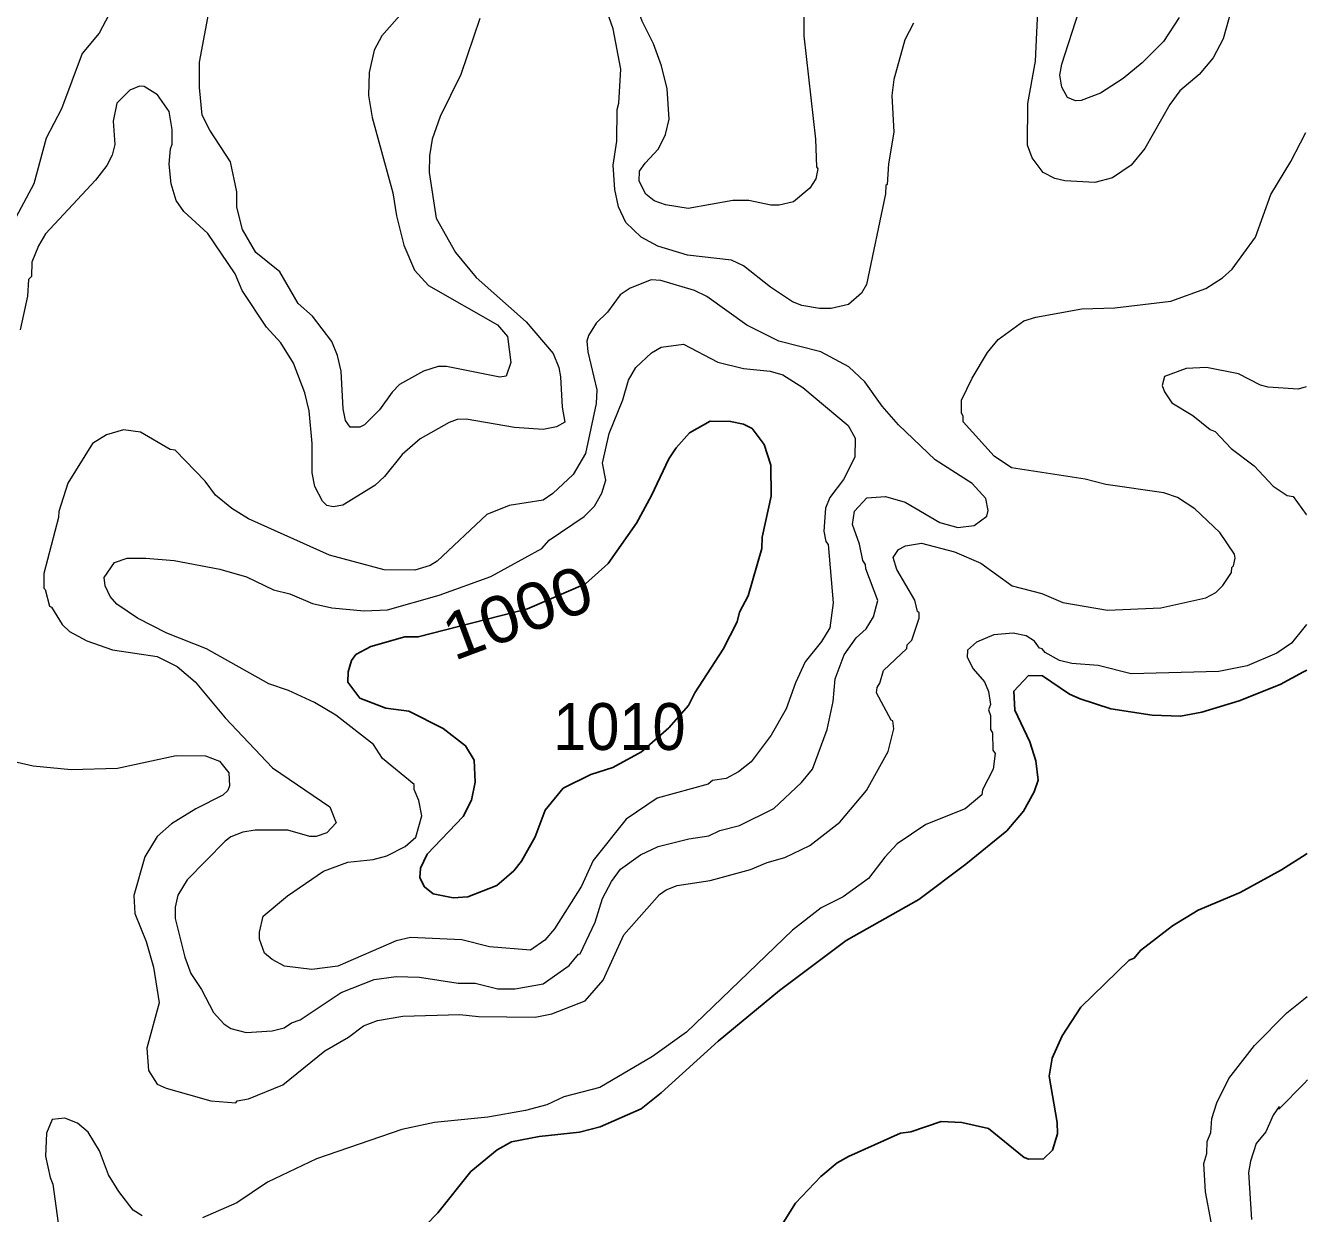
# Model space of a CAD drawing. Extents: x 447.8 to 473.9, y 7733.1 to 7760.8.
# Drawn here: x 471.729 to 473.918, y 7741.173 to 7743.202 of the extents above; entities that cross this region are included whole.
import ezdxf
from ezdxf.enums import TextEntityAlignment as Align

# ---------------------------------------------------------------- set-up
doc = ezdxf.new("R2010")
doc.units = 0
doc.header["$LTSCALE"] = 0.032
doc.layers.add('1', color=7, linetype='Continuous', lineweight=25)
doc.layers.add('2', color=7, linetype='Continuous', lineweight=13)
doc.layers.add('21', color=7, linetype='Continuous')
doc.layers.add('61', color=7, linetype='Continuous')

msp = doc.modelspace()

# ---------------------------------------------------------------- linework, layer by layer
at = {"layer": '1'}
msp.add_lwpolyline([(472.9864, 7742.3085), (472.9868, 7742.3279), (473.0027, 7742.3978), (473.0019, 7742.451), (472.9907, 7742.4862), (472.9699, 7742.5135), (472.9551, 7742.5208), (472.933, 7742.5255), (472.8981, 7742.5263), (472.8631, 7742.5061), (472.84, 7742.4806), (472.8277, 7742.4617), (472.798, 7742.399), (472.7721, 7742.3519), (472.724, 7742.2829), (472.6852, 7742.2483), (472.5862, 7742.2057), (472.3996, 7742.1574), (472.3767, 7742.1576), (472.3187, 7742.1414), (472.2928, 7742.1273), (472.2855, 7742.117), (472.2797, 7742.0978), (472.279, 7742.0802), (472.2998, 7742.0527), (472.3443, 7742.0358), (472.3835, 7742.0308), (472.4421, 7742.0012), (472.4803, 7741.9712), (472.4953, 7741.9471), (472.4969, 7741.9091), (472.4905, 7741.8787), (472.4764, 7741.8508), (472.4148, 7741.7865), (472.4031, 7741.7624), (472.4024, 7741.746), (472.4101, 7741.7303), (472.4248, 7741.7188), (472.4593, 7741.712), (472.4841, 7741.7136), (472.5335, 7741.7326), (472.5629, 7741.7579), (472.576, 7741.7744), (472.5994, 7741.8158), (472.6165, 7741.8616), (472.6471, 7741.8992), (472.6946, 7741.9223), (472.7319, 7741.9347), (472.7807, 7741.9613), (472.8275, 7742.0024), (472.8614, 7742.0404), (472.8723, 7742.0617), (472.9206, 7742.1365), (472.9442, 7742.1832), (472.9484, 7742.1996), (472.9633, 7742.2278)], close=True, dxfattribs=at)
for points in [[(472.3917, 7741.1313), (472.4327, 7741.1737), (472.4892, 7741.2441), (472.5344, 7741.2814), (472.5591, 7741.2952), (472.6061, 7741.3039), (472.6751, 7741.3117), (472.7104, 7741.3203), (472.7802, 7741.3514), (472.8147, 7741.3787), (472.912, 7741.4671), (473.0166, 7741.5535), (473.1307, 7741.639), (473.2548, 7741.7087), (473.3352, 7741.7694), (473.4049, 7741.8263), (473.4338, 7741.8601), (473.4516, 7741.8931), (473.4587, 7741.9125), (473.4548, 7741.946), (473.4443, 7741.9784), (473.4188, 7742.0321), (473.4173, 7742.0646), (473.4423, 7742.0918), (473.4662, 7742.0908), (473.5123, 7742.0599), (473.5302, 7742.0516), (473.5827, 7742.0349), (473.6532, 7742.0237), (473.7019, 7742.0221), (473.7381, 7742.029), (473.8022, 7742.0481), (473.8722, 7742.0764), (473.9118, 7742.0976), (473.9174, 7742.1006)], [(473.9179, 7741.7874), (473.9166, 7741.7866), (473.8744, 7741.7594), (473.8035, 7741.7208), (473.7319, 7741.6905), (473.6883, 7741.6642), (473.6334, 7741.6219), (473.6226, 7741.6088), (473.6141, 7741.6051), (473.5316, 7741.5249), (473.4997, 7741.476), (473.4826, 7741.4381), (473.4774, 7741.407), (473.4908, 7741.328), (473.4917, 7741.3088), (473.483, 7741.2809), (473.4679, 7741.2657), (473.4429, 7741.2655), (473.4349, 7741.2679), (473.3739, 7741.3175), (473.3282, 7741.3278), (473.2931, 7741.3295), (473.2412, 7741.3121), (473.2233, 7741.3095), (473.1347, 7741.2701), (473.1152, 7741.259), (473.0875, 7741.2356), (473.0442, 7741.19), (472.9609, 7741.0576)]]:
    msp.add_lwpolyline(points, dxfattribs=at)
at = {"layer": '2'}
for points in [[(472.0434, 7743.023), (472.0305, 7743.049), (472.0258, 7743.0961), (472.0257, 7743.1391), (472.04, 7743.215), (472.0416, 7743.2798)], [(471.8817, 7743.2407), (471.8541, 7743.1888), (471.8256, 7743.1544), (471.7898, 7743.0599), (471.7638, 7743.0096), (471.7425, 7742.9316), (471.7035, 7742.8578), (471.6892, 7742.84), (471.679, 7742.8333), (471.657, 7742.8366), (471.6426, 7742.8579), (471.6352, 7742.9095), (471.632, 7742.974), (471.6265, 7742.999), (471.617, 7743.0242), (471.6129, 7743.0499), (471.6121, 7743.14), (471.6292, 7743.1973), (471.6427, 7743.22)], [(473.7927, 7743.2439), (473.7748, 7743.1791), (473.7578, 7743.1469), (473.7336, 7743.1185), (473.7008, 7743.0904), (473.6838, 7743.0668), (473.641, 7742.9919), (473.6175, 7742.9633), (473.5858, 7742.9417), (473.5556, 7742.9336), (473.5041, 7742.9364), (473.4873, 7742.9405), (473.4672, 7742.9511), (473.4482, 7742.9759), (473.4405, 7742.9973), (473.4408, 7743.0687), (473.4541, 7743.141), (473.4589, 7743.2516)], [(472.3849, 7743.2384), (472.3371, 7743.1846), (472.324, 7743.1599), (472.3159, 7743.1218), (472.3143, 7743.0823), (472.3205, 7743.0448), (472.3559, 7742.9163), (472.3624, 7742.8771), (472.375, 7742.8268), (472.3929, 7742.7843), (472.4168, 7742.7577), (472.5351, 7742.6906), (472.5519, 7742.6709), (472.5578, 7742.6264), (472.5499, 7742.6029), (472.5389, 7742.6011), (472.4479, 7742.6193), (472.4337, 7742.6192), (472.4085, 7742.6112), (472.3677, 7742.5886), (472.3549, 7742.5757), (472.3332, 7742.5454), (472.3075, 7742.5199), (472.2995, 7742.5159), (472.2833, 7742.516), (472.2755, 7742.5273), (472.271, 7742.5469), (472.2677, 7742.6117), (472.2618, 7742.6381), (472.252, 7742.662), (472.2186, 7742.7054), (472.1946, 7742.727), (472.163, 7742.781), (472.122, 7742.8142), (472.0994, 7742.8535), (472.0898, 7742.8915), (472.0897, 7742.9179), (472.0785, 7742.9689), (472.0434, 7743.023)], [(473.2455, 7743.2059), (473.231, 7743.1776), (473.212, 7743.1099), (473.2087, 7743.0822), (473.2119, 7743.0198), (473.2027, 7742.9659), (473.2007, 7742.9306), (473.1982, 7742.9286), (473.1975, 7742.9147), (473.1652, 7742.7594), (473.1568, 7742.7445), (473.1343, 7742.7256), (473.105, 7742.7188), (473.085, 7742.7188), (473.0548, 7742.7239), (473.0391, 7742.7298), (473.0011, 7742.7549), (472.9549, 7742.7914), (472.9349, 7742.8012), (472.8593, 7742.8098), (472.809, 7742.8248), (472.7806, 7742.8404), (472.754, 7742.8654), (472.7418, 7742.8924), (472.7351, 7742.922), (472.7326, 7742.9632), (472.739, 7743.0042), (472.7391, 7743.0583), (472.7422, 7743.0693), (472.7454, 7743.1275), (472.7327, 7743.1961), (472.7182, 7743.2368)], [(472.828, 7743.0418), (472.8248, 7743.0938), (472.815, 7743.133), (472.8015, 7743.1708), (472.7822, 7743.2096), (472.7726, 7743.2356)], [(473.058, 7743.2269), (473.0582, 7743.1842), (473.0782, 7743.0077), (473.0798, 7742.9604), (473.082, 7742.9573), (473.0787, 7742.9401), (473.0685, 7742.9239), (473.0407, 7742.9008), (473.016, 7742.8952), (473.0016, 7742.8951), (472.9642, 7742.9031), (472.9371, 7742.9031), (472.8609, 7742.8894), (472.8222, 7742.8959), (472.8024, 7742.9026), (472.7884, 7742.9138), (472.7767, 7742.9359), (472.7777, 7742.9529), (472.7869, 7742.9669), (472.8097, 7742.9915), (472.822, 7743.0157), (472.828, 7743.0418)], [(473.6992, 7743.2155), (473.6726, 7743.1745), (473.6365, 7743.1384), (473.6037, 7743.1113), (473.5652, 7743.0865), (473.5323, 7743.0738), (473.5223, 7743.0731), (473.5085, 7743.0789), (473.4991, 7743.0969), (473.4958, 7743.117), (473.4991, 7743.1362), (473.5278, 7743.2257)], [(472.5048, 7743.2139), (472.4722, 7743.1182), (472.4371, 7743.0463), (472.4234, 7743.008), (472.4185, 7742.9791), (472.4183, 7742.9507), (472.4304, 7742.8729), (472.4634, 7742.8144), (472.4986, 7742.7715), (472.5841, 7742.6956), (472.63, 7742.6417), (472.6396, 7742.6177), (472.6428, 7742.6017), (472.6453, 7742.5499), (472.65, 7742.5245), (472.6359, 7742.5165), (472.613, 7742.512), (472.5637, 7742.5152), (472.4816, 7742.5295), (472.466, 7742.5287), (472.4523, 7742.524), (472.4026, 7742.4961), (472.3723, 7742.4689), (472.342, 7742.4315), (472.3256, 7742.4164), (472.2709, 7742.3824), (472.2544, 7742.3797), (472.2433, 7742.3822), (472.236, 7742.3896), (472.2229, 7742.4142), (472.2181, 7742.4378), (472.218, 7742.4881), (472.2132, 7742.544), (472.2057, 7742.5745), (472.1862, 7742.6251), (472.1649, 7742.6597), (472.1402, 7742.6865), (472.0984, 7742.7495), (472.0865, 7742.778), (472.0398, 7742.8464), (471.999, 7742.8841), (471.9857, 7742.9028), (471.9776, 7742.9316), (471.9739, 7742.9651), (471.976, 7742.9912), (471.9791, 7742.9994), (471.9792, 7743.0241), (471.9737, 7743.0548), (471.9543, 7743.0834), (471.931, 7743.0978), (471.9231, 7743.0985), (471.9068, 7743.0913), (471.8848, 7743.0692), (471.8782, 7743.0388), (471.8812, 7742.9987), (471.8766, 7742.9803), (471.8675, 7742.9626), (471.8481, 7742.9378), (471.7627, 7742.8462), (471.7506, 7742.8258), (471.7395, 7742.7976), (471.7386, 7742.773), (471.7339, 7742.7681), (471.7322, 7742.7396), (471.7195, 7742.6821)], [(473.1944, 7742.0999), (473.2343, 7742.1376), (473.2349, 7742.144), (473.2426, 7742.1519), (473.2552, 7742.1898), (473.2552, 7742.1989), (473.2522, 7742.201), (473.2478, 7742.2203), (473.2172, 7742.2724), (473.2106, 7742.2932), (473.2199, 7742.3071), (473.2319, 7742.3132), (473.259, 7742.3179), (473.3156, 7742.3029), (473.3607, 7742.2836), (473.4141, 7742.2447), (473.4649, 7742.2314), (473.5007, 7742.2165), (473.5772, 7742.2034), (473.6679, 7742.2074), (473.7448, 7742.2244), (473.7623, 7742.2333), (473.7743, 7742.2453), (473.7891, 7742.2678), (473.7892, 7742.2759), (473.7922, 7742.2787), (473.7953, 7742.292), (473.7939, 7742.2987), (473.7688, 7742.3357), (473.726, 7742.3761), (473.6964, 7742.3956), (473.6734, 7742.4038), (473.5743, 7742.4178), (473.5387, 7742.427), (473.4133, 7742.4465), (473.3834, 7742.4663), (473.3307, 7742.5251), (473.3306, 7742.5348), (473.3275, 7742.5395), (473.3275, 7742.562), (473.3456, 7742.5996), (473.3718, 7742.6436), (473.3905, 7742.6655), (473.4339, 7742.6974), (473.4544, 7742.7036), (473.533, 7742.718), (473.5894, 7742.7196), (473.6855, 7742.7313), (473.7448, 7742.7527), (473.7733, 7742.7707), (473.7902, 7742.7858), (473.8298, 7742.8405), (473.8559, 7742.9134), (473.8904, 7742.9694), (473.907, 7743.0018), (473.916, 7743.0194)], [(473.2827, 7742.4598), (473.2201, 7742.5198), (473.1918, 7742.5519), (473.1624, 7742.5935), (473.1352, 7742.6187), (473.0871, 7742.6444), (473.0157, 7742.6629), (472.9609, 7742.6903), (472.8923, 7742.7391), (472.8716, 7742.7491), (472.8141, 7742.7661), (472.7975, 7742.7676), (472.7616, 7742.7533), (472.7447, 7742.742), (472.7228, 7742.7121), (472.7036, 7742.6936), (472.6902, 7742.6722), (472.6878, 7742.6629), (472.6892, 7742.6444), (472.7044, 7742.5795), (472.7037, 7742.5565), (472.6854, 7742.4711), (472.6639, 7742.4352), (472.6297, 7742.4026), (472.6127, 7742.391), (472.5547, 7742.382), (472.5168, 7742.3664), (472.4317, 7742.2871), (472.4198, 7742.2793), (472.3934, 7742.2715), (472.3414, 7742.2719), (472.2478, 7742.2974), (472.1097, 7742.3594), (472.0809, 7742.3768), (472.0532, 7742.3995), (472.0352, 7742.4237), (471.984, 7742.4764), (471.9757, 7742.4778), (471.9249, 7742.507), (471.8958, 7742.5111), (471.8667, 7742.503), (471.8431, 7742.4877), (471.801, 7742.4201), (471.7853, 7742.3715), (471.7851, 7742.3613), (471.7597, 7742.2657), (471.7596, 7742.2406), (471.7621, 7742.2387), (471.7693, 7742.2099), (471.7727, 7742.2083), (471.7913, 7742.1787), (471.8035, 7742.1667), (471.8332, 7742.1509), (471.8771, 7742.1355), (471.9535, 7742.1239), (471.9877, 7742.1067), (472.0181, 7742.0809), (472.0695, 7742.0191), (472.1506, 7741.9341), (472.2483, 7741.8674), (472.2595, 7741.8401), (472.2434, 7741.8226), (472.2251, 7741.8163), (472.2144, 7741.8163), (472.1766, 7741.8273), (472.121, 7741.8274), (472.0997, 7741.8242), (472.0792, 7741.8157), (472.0694, 7741.8086), (472.0048, 7741.7424), (471.9887, 7741.7164), (471.984, 7741.6959), (471.984, 7741.6763), (472.0009, 7741.6106), (472.0111, 7741.5824), (472.0292, 7741.555), (472.0498, 7741.5161), (472.0671, 7741.4965), (472.0796, 7741.4887), (472.1055, 7741.482), (472.1498, 7741.4844), (472.1704, 7741.4895), (472.1829, 7741.4983), (472.1979, 7741.5032), (472.2678, 7741.55), (472.3241, 7741.5725), (472.362, 7741.5772), (472.4014, 7741.5764), (472.4678, 7741.5661), (472.4966, 7741.5661), (472.5355, 7741.5565), (472.565, 7741.5565), (472.6127, 7741.5646), (472.6571, 7741.5963), (472.6731, 7741.6153)], [(471.9197, 7742.1897), (471.8843, 7742.2133), (471.8731, 7742.2264), (471.8646, 7742.2446), (471.8632, 7742.259), (471.8805, 7742.2847), (471.9022, 7742.2919), (471.9339, 7742.2923), (471.9823, 7742.2882), (472.0606, 7742.2731), (472.1061, 7742.2601), (472.1523, 7742.2378), (472.1803, 7742.2312), (472.2187, 7742.2144), (472.252, 7742.2073), (472.3072, 7742.2018), (472.3468, 7742.2035), (472.4354, 7742.2287), (472.5236, 7742.2608), (472.6109, 7742.3086), (472.6234, 7742.3225), (472.6827, 7742.3634), (472.7008, 7742.3809), (472.7134, 7742.403), (472.7197, 7742.4253), (472.7143, 7742.4545), (472.7254, 7742.5052), (472.7489, 7742.5623), (472.7586, 7742.596), (472.7714, 7742.618), (472.7978, 7742.6429), (472.8143, 7742.6523), (472.8529, 7742.6578), (472.9113, 7742.6271), (472.9554, 7742.6161), (473.0007, 7742.6113), (473.0222, 7742.6052), (473.0567, 7742.5838), (473.1341, 7742.5189), (473.1462, 7742.4972), (473.1455, 7742.4645), (473.1261, 7742.4263), (473.1026, 7742.3959), (473.095, 7742.3772), (473.0926, 7742.3384), (473.0956, 7742.3205), (473.0998, 7742.3156), (473.1085, 7742.216), (473.1029, 7742.1732), (473.0885, 7742.1497), (473.0603, 7742.1148), (473.0438, 7742.0793), (473.0278, 7742.0344), (473.0023, 7741.9899), (472.9685, 7741.9439), (472.9469, 7741.9269), (472.9253, 7741.9158), (472.9024, 7741.9121), (472.895, 7741.906), (472.8078, 7741.8821), (472.7548, 7741.8464), (472.6986, 7741.7754), (472.6785, 7741.7317), (472.6324, 7741.659), (472.6159, 7741.6394), (472.5911, 7741.6222), (472.5212, 7741.6282), (472.4738, 7741.6399), (472.3865, 7741.644), (472.362, 7741.6381), (472.262, 7741.5952), (472.2176, 7741.5894), (472.1709, 7741.5952), (472.1501, 7741.6062), (472.1367, 7741.6171), (472.1283, 7741.6411), (472.1283, 7741.653), (472.1347, 7741.6803), (472.1761, 7741.7154), (472.2379, 7741.7571), (472.2793, 7741.7729), (472.3227, 7741.7774), (472.3456, 7741.7838), (472.377, 7741.7995), (472.3955, 7741.8152), (472.4057, 7741.8517), (472.4007, 7741.8781), (472.3928, 7741.8967), (472.3927, 7741.9056), (472.3383, 7741.95), (472.3228, 7741.9735), (472.2586, 7742.0241), (472.2222, 7742.0457), (472.1779, 7742.0662), (472.1445, 7742.0773)], [(473.9166, 7742.5848), (473.9029, 7742.5809), (473.8513, 7742.5841), (473.8382, 7742.5876), (473.801, 7742.607), (473.7461, 7742.6178), (473.7112, 7742.6162), (473.6747, 7742.6024), (473.6706, 7742.5872), (473.6744, 7742.5763), (473.6872, 7742.5571), (473.7229, 7742.5357), (473.7525, 7742.5118), (473.761, 7742.5086), (473.7886, 7742.4796), (473.8274, 7742.4496), (473.8598, 7742.4148), (473.884, 7742.3989), (473.8941, 7742.3972), (473.9166, 7742.3669), (473.917, 7742.3664)], [(472.7453, 7741.7606), (472.779, 7741.7851), (472.8095, 7741.7996), (472.8618, 7741.8128), (472.8958, 7741.8177), (472.9149, 7741.8269), (472.9481, 7741.8356), (473.007, 7741.8645), (473.0545, 7741.9087), (473.0733, 7741.9316), (473.0982, 7741.9992), (473.1085, 7742.047), (473.1118, 7742.0857), (473.127, 7742.1269), (473.1476, 7742.1557), (473.1645, 7742.1713), (473.1773, 7742.1918), (473.1847, 7742.2196), (473.164, 7742.2739), (473.1637, 7742.281), (473.159, 7742.2878), (473.1535, 7742.316), (473.1416, 7742.3497), (473.1447, 7742.3724), (473.1658, 7742.3951), (473.198, 7742.3973), (473.2312, 7742.3877), (473.2908, 7742.3532), (473.3213, 7742.3445), (473.3491, 7742.3478), (473.3707, 7742.364), (473.373, 7742.3732), (473.3691, 7742.394), (473.3461, 7742.4195), (473.2827, 7742.4598)], [(472.1445, 7742.0773), (472.0379, 7742.1374), (471.9702, 7742.1638), (471.9197, 7742.1897)], [(473.9173, 7742.1786), (473.9126, 7742.1729), (473.8912, 7742.1469), (473.8662, 7742.13), (473.8154, 7742.1081), (473.7673, 7742.0984), (473.6172, 7742.0944), (473.5611, 7742.1088), (473.5163, 7742.112), (473.4948, 7742.1173), (473.4704, 7742.1311), (473.4652, 7742.1374), (473.4609, 7742.138), (473.4522, 7742.1505), (473.438, 7742.1592), (473.416, 7742.164), (473.3827, 7742.1608), (473.353, 7742.1488), (473.3379, 7742.1351), (473.3371, 7742.1228), (473.3475, 7742.1031), (473.3671, 7742.0807), (473.374, 7742.0644), (473.3771, 7742.0418), (473.374, 7742.0328), (473.3771, 7742.0235), (473.3772, 7741.9992), (473.3803, 7741.9937), (473.3812, 7741.9643), (473.3852, 7741.9581), (473.3819, 7741.9315), (473.3635, 7741.896), (473.3624, 7741.8875), (473.3341, 7741.8636), (473.2668, 7741.8372), (473.2179, 7741.8043), (473.1965, 7741.7814), (473.1685, 7741.7446), (473.1257, 7741.7137), (473.088, 7741.6945), (473.0387, 7741.6568), (472.8579, 7741.4822), (472.7996, 7741.4406), (472.7096, 7741.3879), (472.6481, 7741.3719), (472.6194, 7741.3579), (472.5825, 7741.3482), (472.5185, 7741.3369), (472.4273, 7741.3278), (472.3716, 7741.3158), (472.2257, 7741.2661), (472.142, 7741.2258), (472.0894, 7741.1908), (472.031, 7741.165)], [(473.2104, 7742.0144), (473.2073, 7742.0151), (473.1824, 7742.0617), (473.1833, 7742.071), (473.1883, 7742.0785), (473.1944, 7742.0999)], [(471.7143, 7741.9438), (471.7414, 7741.9371), (471.8065, 7741.9308), (471.8858, 7741.9331), (471.9862, 7741.9549), (472.0362, 7741.9541), (472.0601, 7741.9451), (472.076, 7741.9251), (472.0769, 7741.9031), (472.0743, 7741.8954), (472.0654, 7741.8869), (472.0195, 7741.8636), (471.9781, 7741.8382), (471.9537, 7741.8164), (471.9324, 7741.7818), (471.9136, 7741.7158), (471.9154, 7741.6849), (471.9346, 7741.6371), (471.947, 7741.5933), (471.9568, 7741.5326), (471.9358, 7741.4551), (471.9387, 7741.4169), (471.9532, 7741.3934), (471.9688, 7741.3865), (472.0452, 7741.3648), (472.0877, 7741.3617), (472.0902, 7741.3648), (472.1097, 7741.3682), (472.1681, 7741.3921), (472.2398, 7741.4502), (472.2805, 7741.4739), (472.306, 7741.4933), (472.3297, 7741.5023), (472.3732, 7741.5099), (472.4703, 7741.5124), (472.5023, 7741.5092), (472.5994, 7741.5079), (472.6279, 7741.5135), (472.6846, 7741.5359), (472.7152, 7741.5711), (472.7506, 7741.6488), (472.8115, 7741.7175), (472.8232, 7741.7255), (472.8419, 7741.7328), (472.8983, 7741.7414), (472.9674, 7741.7602), (472.9958, 7741.7721), (473.0257, 7741.7807), (473.0687, 7741.8014), (473.1199, 7741.8411), (473.1653, 7741.8953), (473.2022, 7741.9618), (473.2119, 7742.0005), (473.2104, 7742.0144)], [(472.6731, 7741.6153), (472.6764, 7741.616), (472.7015, 7741.6702), (472.7144, 7741.7106), (472.7296, 7741.7395), (472.7453, 7741.7606)], [(473.7544, 7741.1583), (473.7443, 7741.2098), (473.7419, 7741.2578), (473.7467, 7741.2748), (473.7475, 7741.2956), (473.7538, 7741.3111), (473.7555, 7741.3349), (473.7638, 7741.3618), (473.7841, 7741.4034), (473.8284, 7741.4594), (473.8837, 7741.5155), (473.9118, 7741.5381), (473.9183, 7741.5433)], [(473.9185, 7741.4006), (473.9134, 7741.3954), (473.8696, 7741.351), (473.8703, 7741.3553), (473.8601, 7741.3407), (473.8474, 7741.3122), (473.8311, 7741.2922), (473.8213, 7741.2621), (473.818, 7741.2423), (473.8228, 7741.1623)], [(471.9281, 7741.1685), (471.9124, 7741.1784), (471.8879, 7741.2099), (471.8706, 7741.2383), (471.8548, 7741.2794), (471.8355, 7741.3112), (471.8174, 7741.3269), (471.7956, 7741.3352), (471.7743, 7741.3329), (471.7644, 7741.3098), (471.7628, 7741.2707), (471.7704, 7741.2342), (471.7755, 7741.2229), (471.7897, 7741.1182)]]:
    msp.add_lwpolyline(points, dxfattribs=at)

# ---------------------------------------------------------------- texts
at = {"layer": '21', "width": 0.95}
msp.add_text('1010', height=0.08, dxfattribs=at).set_placement((472.6301, 7741.9644))
at = {"layer": '61', "width": 1.1}
msp.add_text('1000', height=0.08, rotation=20.486, dxfattribs=at).set_placement((472.5831, 7742.1618), align=Align.CENTER)

doc.saveas('drawing.dxf')
